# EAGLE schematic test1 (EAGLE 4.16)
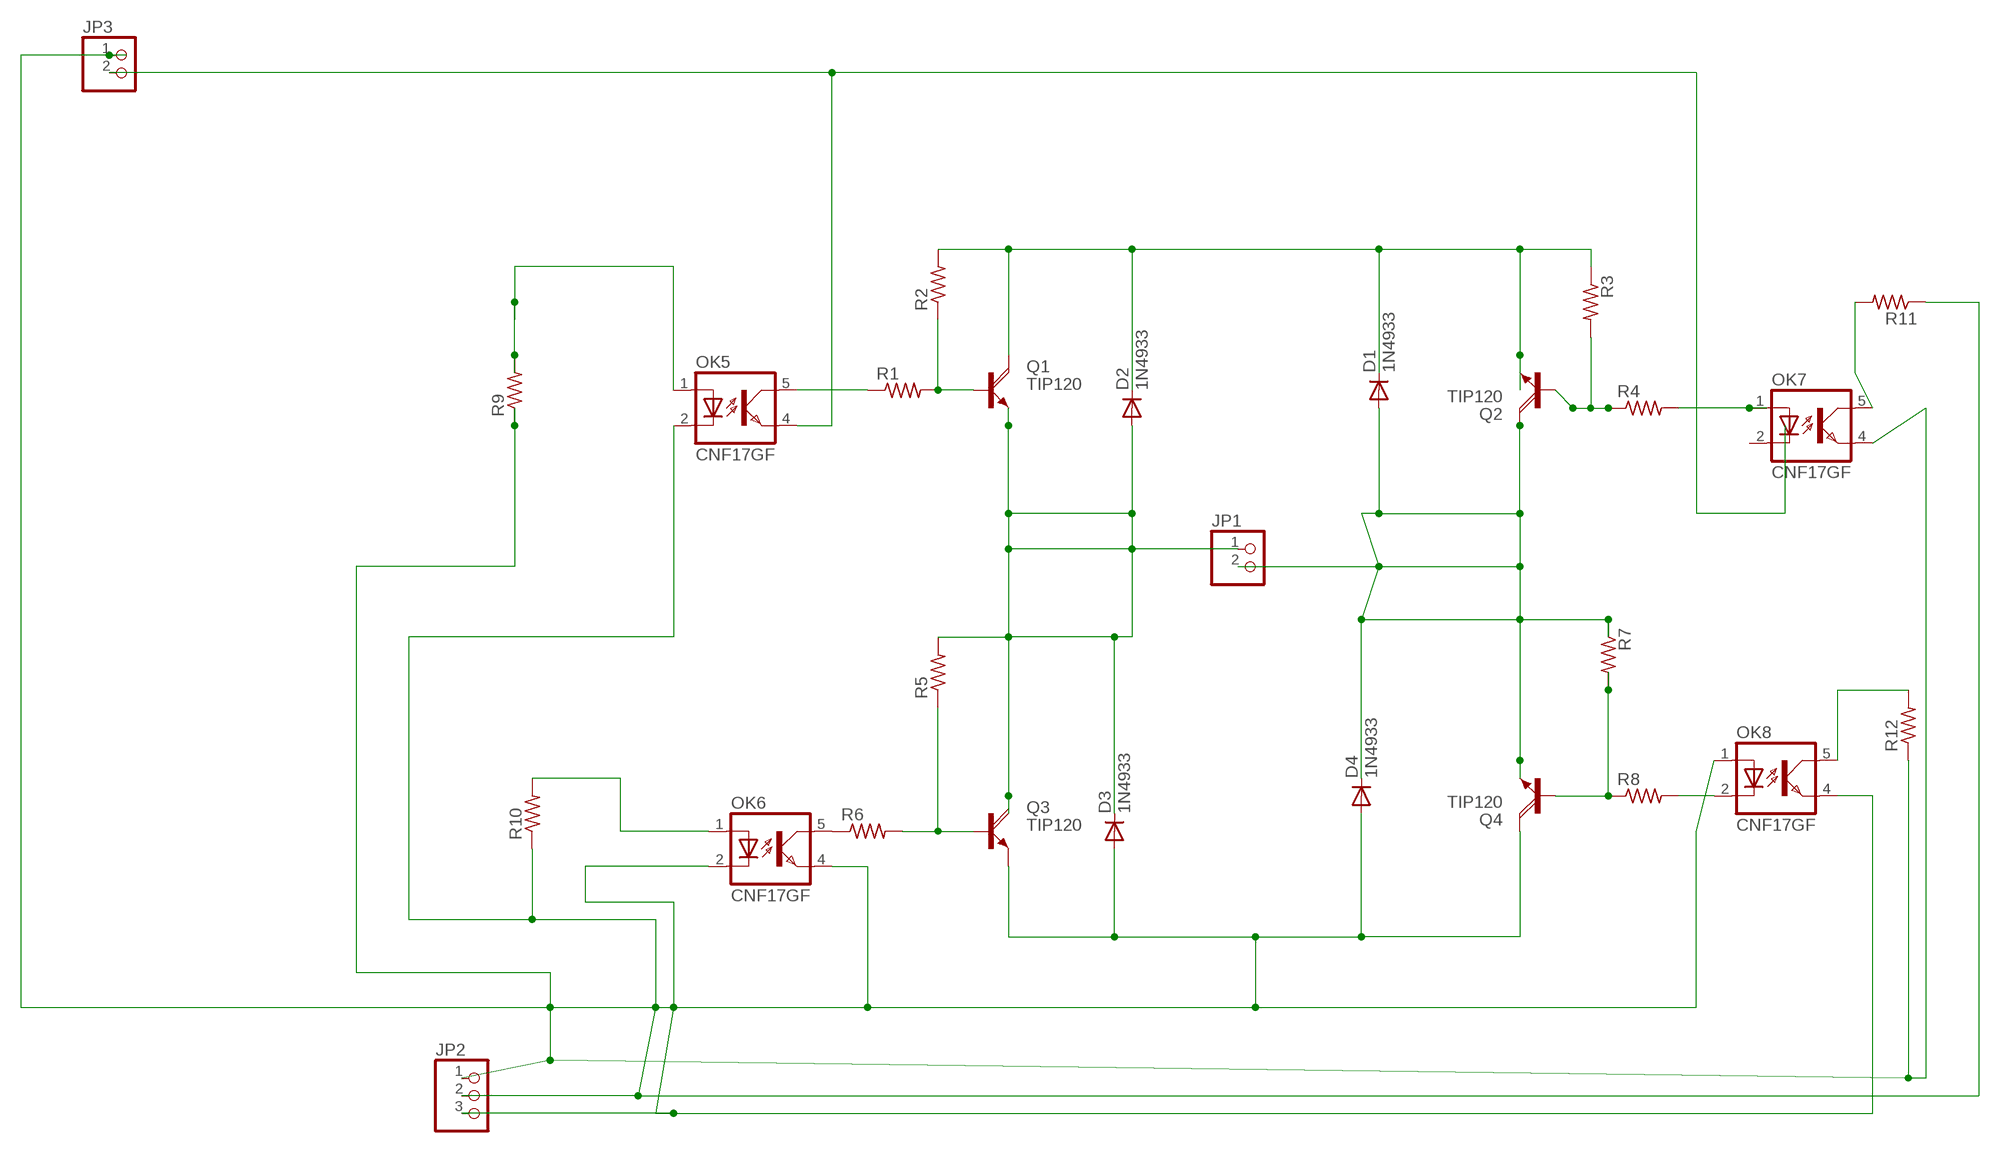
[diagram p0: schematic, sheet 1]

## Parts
D1  1N4933  [DO41-10]
D2  1N4933  [DO41-10]
D3  1N4933  [DO41-10]
D4  1N4933  [DO41-10]
JP1  PINHD-1X2  [1X02]
JP2  PINHD-1X3  [1X03]
JP3  PINHD-1X2  [1X02]
OK5  CNF17GF  [DIL06B]
OK6  CNF17GF  [DIL06B]
OK7  CNF17GF  [DIL06B]
OK8  CNF17GF  [DIL06B]
Q1  TIP120  [TO220AH]
Q2  TIP120  [TO220AH]
Q3  TIP120  [TO220AH]
Q4  TIP120  [TO220AH]
R1  R-US_0204/2V  [0204V]
R2  R-US_0204/2V  [0204V]
R3  R-US_0204/2V  [0204V]
R4  R-US_0204/2V  [0204V]
R5  R-US_0204/2V  [0204V]
R6  R-US_0204/2V  [0204V]
R7  R-US_0204/2V  [0204V]
R8  R-US_0204/2V  [0204V]
R9  R-US_0204/2V  [0204V]
R10  R-US_0204/2V  [0204V]
R11  R-US_0204/2V  [0204V]
R12  R-US_0204/2V  [0204V]

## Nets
N$1: OK5.5(COL) R1.1
N$2: Q1.B R1.2 R2.1
N$3: OK6.5(COL) R6.1
N$4: D1.C D2.C Q1.C Q2.E R2.2 R3.1
N$5: D2.A D3.C JP1.1 Q1.E Q3.C R5.2
N$6: D1.A D4.C JP1.2 Q2.C Q4.E R7.1
N$7: Q2.B R3.2 R4.1
N$8: Q3.B R5.1 R6.2
N$9: OK5.1(A) R9.2
N$10: D3.A D4.A JP2.1 JP2.2 JP2.3 JP3.1 OK5.2(C) OK6.2(C) OK6.4(EMIT) OK7.4(EMIT) OK8.1(A) OK8.4(EMIT) Q3.E Q4.C R9.1 R10.1 R11.1 R12.1
N$11: OK6.1(A) R10.2
N$12: OK7.5(COL) R11.2
N$13: Q4.B R7.2 R8.1
N$14: OK7.1(A) R4.2
N$15: OK8.2(C) R8.2
N$17: JP3.2 OK5.4(EMIT)
N$18: OK8.5(COL) R12.2
Unconnected: OK7.2(C)

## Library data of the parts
D1-D4 = diode:1N4933: DIODE
JP1 JP3 = pinhead:PINHD-1X2: PIN HEADER
JP2 = pinhead:PINHD-1X3: PIN HEADER
OK5-OK8 = optocoupler:CNF17GF: HEWLETT PACKARD OPTO COUPLER
Q1-Q4 = transistor-power:TIP120: NPN DARLINGTON TRANSISTOR
R1-R12 = rcl:R-US_: RESISTOR, American symbol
